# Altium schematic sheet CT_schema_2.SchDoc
size 366 x 279 mm
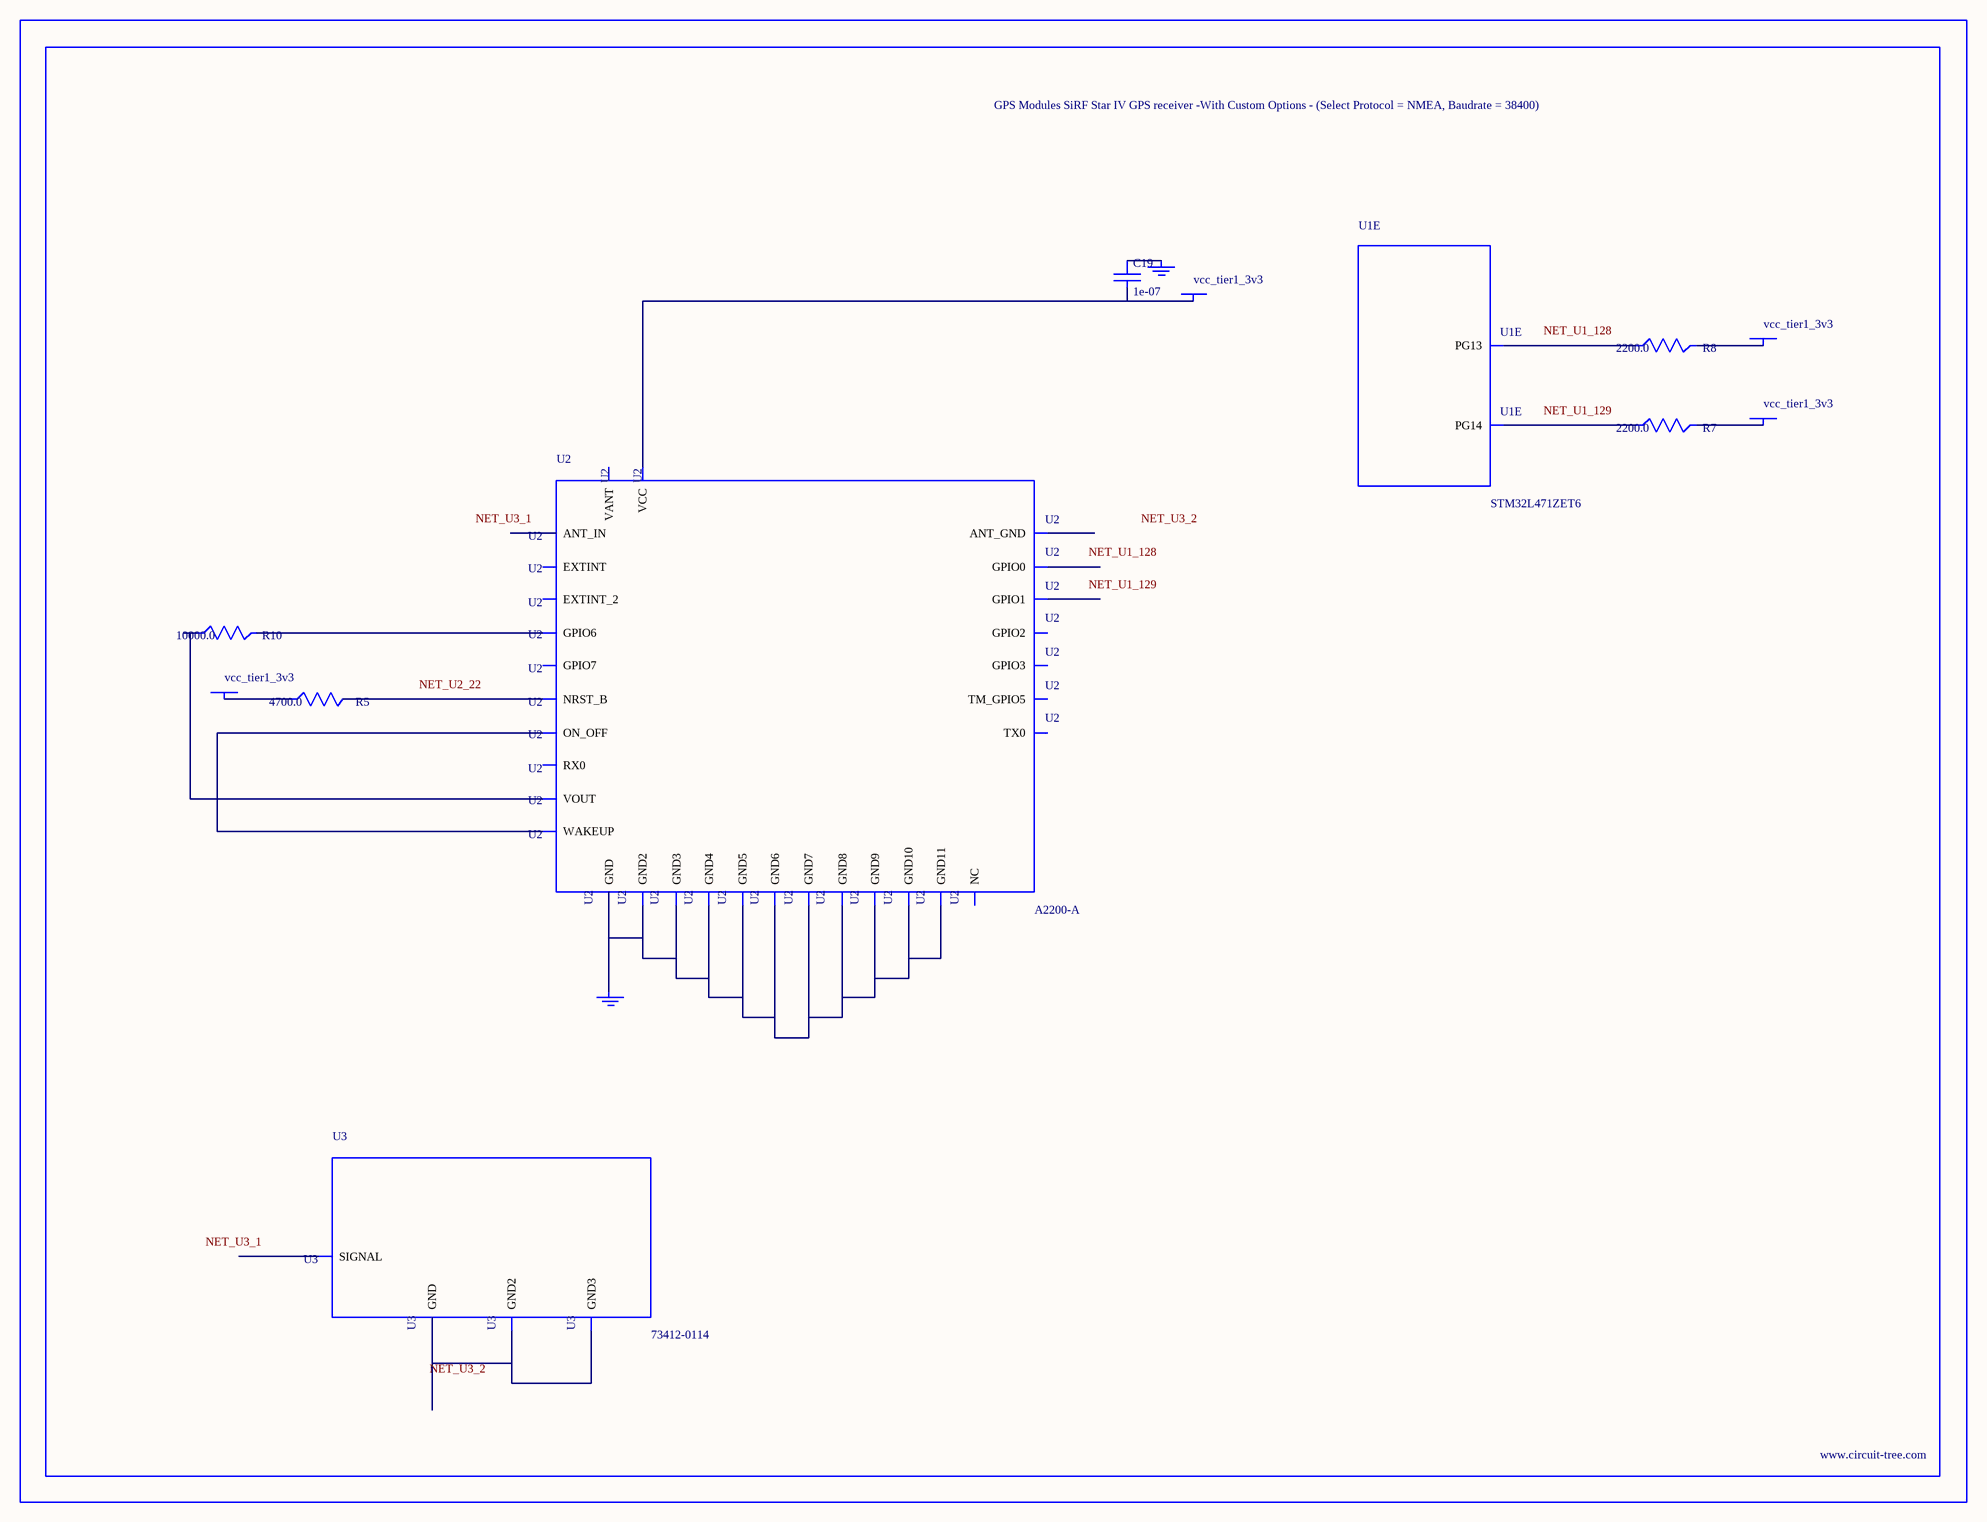
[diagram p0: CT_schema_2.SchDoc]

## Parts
BORDER1  (no value)
C19  1e-07  [C0402]
GND_INSTANCE_1_0  (no value)
GND_INSTANCE_1_1  (no value)
POWER_INSTANCE_1_0  vcc_tier1_3v3
POWER_INSTANCE_1_1  vcc_tier1_3v3
POWER_INSTANCE_1_2  vcc_tier1_3v3
POWER_INSTANCE_1_3  vcc_tier1_3v3
R5  4700.0  [R0603]
R7  2200.0  [R0603]
R8  2200.0  [R0603]
R10  10000.0  [R0603]
U1  STM32L471ZET6  [LQFP144]  (part E of 13)
U2  A2200-A  [A2200-A]
U3  73412-0114  [COAXIAL_C]

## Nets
NetC19_1: C19.1 GND_INSTANCE_1_0.0(GND)
NetC19_2: C19.2 POWER_INSTANCE_1_0.0(PWR) U2.20(VCC)
NetGND_INSTANCE_1_1_0: GND_INSTANCE_1_1.0(GND) U2.7(GND) U2.8(GND2) U2.23(GND3) U2.24(GND4) U2.25(GND5) U2.26(GND6) U2.27(GND7) U2.28(GND8) U2.29(GND9) U2.30(GND10) U2.31(GND11)
NetPOWER_INSTANCE_1_1_0: POWER_INSTANCE_1_1.0(PWR) R5.1
NetPOWER_INSTANCE_1_2_0: POWER_INSTANCE_1_2.0(PWR) R8.2
NetPOWER_INSTANCE_1_3_0: POWER_INSTANCE_1_3.0(PWR) R7.2
NetR5_2: R5.2 U2.22(NRST_B)
NetR7_1: R7.1 U1.129(PG14)
NetR8_1: R8.1 U1.128(PG13)
NetR10_1: R10.1 U2.2(VOUT)
NetR10_2: R10.2 U2.17(GPIO6)
NetU2_6: U2.6(ON_OFF) U2.19(WAKEUP)
NetU3_2: U3.2(GND) U3.3(GND2) U3.4(GND3)

Not connected (* = marked no-connect by the designer): U2 1(GPIO2) 3(TX0) 4(RX0) 5(EXTINT_2) 9(VANT) 10(ANT_GND) 11(ANT_IN) 12(GPIO3) 13(EXTINT) 14(TM_GPIO5) 15(GPIO1) 16(GPIO0) 18(GPIO7) 21(NC); U3 1(SIGNAL)

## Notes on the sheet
- Labels drawn without touching a wire or pin: NET_U1_128, NET_U1_129, NET_U2_22, NET_U3_1, NET_U3_2

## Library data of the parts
BORDER1 = BORDER_PAGE1
C19 = C0402C104K3RACTU
GND_INSTANCE_1_0 GND_INSTANCE_1_1 = GND
POWER_INSTANCE_1_0-POWER_INSTANCE_1_3 = PWR
R5 = RC0603JR-074K7L
R7 R8 = RC0603JR-072K2L
R10 = RC0603JR-0710KL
